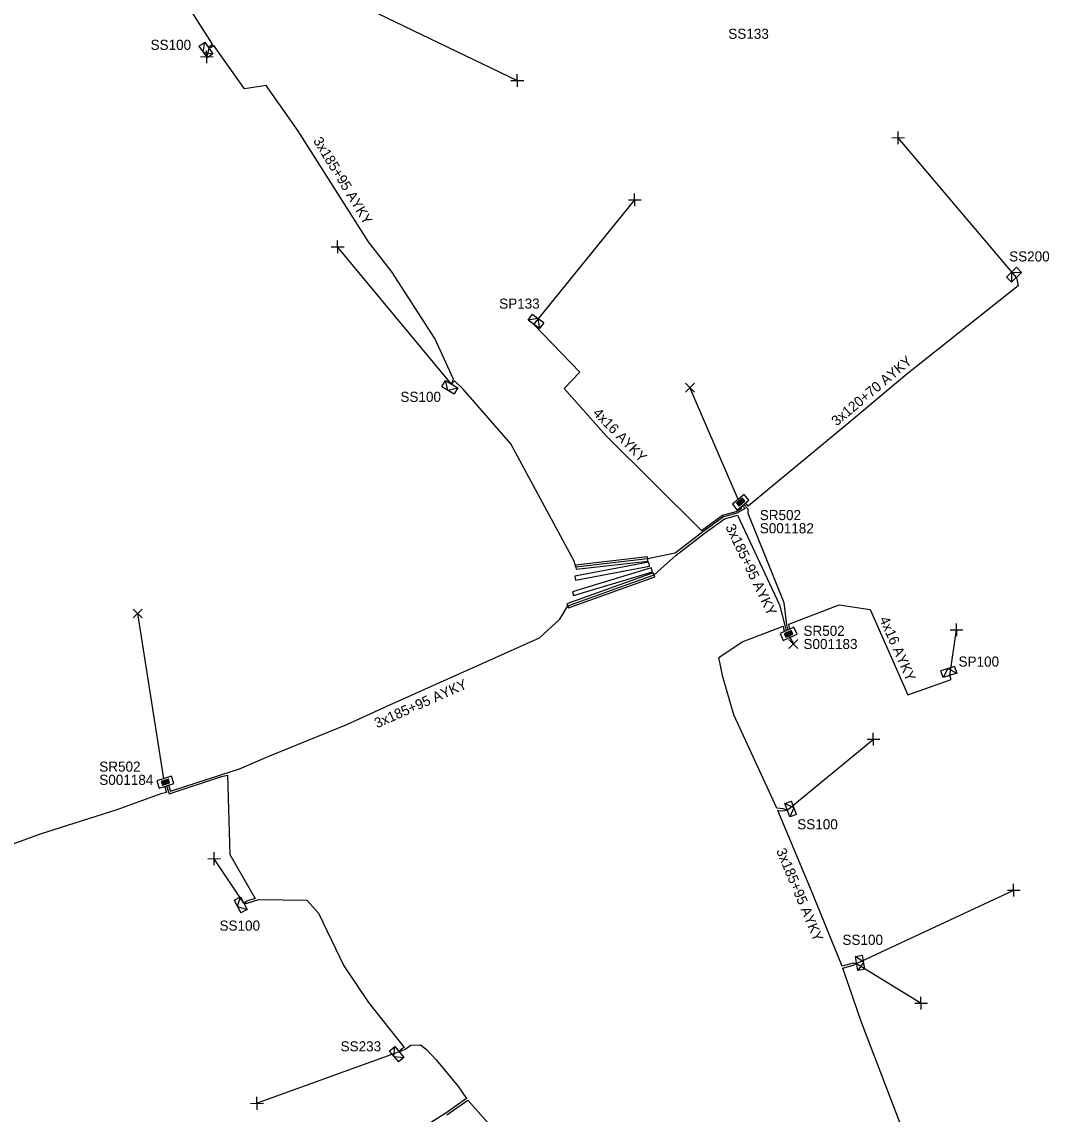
# Model space of a CAD drawing. Extents: x -762504 to -761250, y -1152974 to -1152253.
# Drawn here: x -761655.3 to -761554.2, y -1152498.6 to -1152391 of the extents above; entities that cross this region are included whole.
import ezdxf

# ---------------------------------------------------------------- set-up
doc = ezdxf.new("R2010")
doc.units = 0
for name, color, linetype in [('Vrstva 20', 7, 'Continuous'), ('Vrstva 28', 7, 'Continuous'), ('Vrstva 29', 7, 'Continuous'), ('Vrstva 30', 7, 'Continuous'), ('Vrstva 31', 7, 'Continuous'), ('Vrstva 33', 7, 'Continuous'), ('Vrstva 34', 7, 'Continuous'), ('Vrstva 5', 7, 'Continuous'), ('Vrstva 59', 7, 'Continuous'), ('Vrstva 6', 7, 'Continuous')]:
    doc.layers.add(name, color=color, linetype=linetype)

msp = doc.modelspace()

# ---------------------------------------------------------------- linework, layer by layer
at = {"layer": 'Vrstva 20'}
for points in [[(-761593.62, -1152444.18), (-761600.9, -1152445.56), (-761600.82, -1152445.96), (-761593.54, -1152444.58)], [(-761593.76, -1152443.68), (-761600.82, -1152444.49), (-761600.78, -1152444.89), (-761593.72, -1152444.08)], [(-761593.17, -1152445.25), (-761601.67, -1152448.3), (-761601.53, -1152448.68), (-761593.03, -1152445.63)], [(-761593.37, -1152444.75), (-761601.14, -1152447.11), (-761601.02, -1152447.49), (-761593.25, -1152445.13)]]:
    msp.add_lwpolyline(points, close=True, dxfattribs=at)
at = {"layer": 'Vrstva 28'}
for points in [[(-761584.237, -1152437.517), (-761585.386, -1152438.482)], [(-761584.4, -1152437.901), (-761584.97, -1152438.38)], [(-761584.406, -1152437.968), (-761584.904, -1152438.385)], [(-761584.904, -1152439.056), (-761583.755, -1152438.092)], [(-761584.412, -1152438.034), (-761584.837, -1152438.391)], [(-761584.418, -1152438.101), (-761584.771, -1152438.397)], [(-761584.357, -1152438.173), (-761584.418, -1152438.101)], [(-761584.291, -1152438.179), (-761584.412, -1152438.034)], [(-761584.224, -1152438.185), (-761584.406, -1152437.968)], [(-761584.157, -1152438.191), (-761584.4, -1152437.901)], [(-761583.755, -1152438.092), (-761584.237, -1152437.517)], [(-761585.386, -1152438.482), (-761584.904, -1152439.056)], [(-761584.97, -1152438.38), (-761584.728, -1152438.669)], [(-761584.904, -1152438.385), (-761584.722, -1152438.603)], [(-761584.837, -1152438.391), (-761584.716, -1152438.536)], [(-761584.771, -1152438.397), (-761584.71, -1152438.469)], [(-761584.728, -1152438.669), (-761584.157, -1152438.191)], [(-761584.722, -1152438.603), (-761584.224, -1152438.185)], [(-761584.716, -1152438.536), (-761584.291, -1152438.179)], [(-761584.71, -1152438.469), (-761584.357, -1152438.173)], [(-761584.419, -1152438.164), (-761584.709, -1152438.407)], [(-761579.33, -1152450.599), (-761580.689, -1152451.233)], [(-761579.6, -1152450.927), (-761580.275, -1152451.242)], [(-761579.623, -1152450.99), (-761580.212, -1152451.264)], [(-761579.503, -1152451.247), (-761579.623, -1152450.99)], [(-761579.441, -1152451.27), (-761579.6, -1152450.927)], [(-761579.013, -1152451.279), (-761579.33, -1152450.599)], [(-761580.689, -1152451.233), (-761580.372, -1152451.913)], [(-761580.372, -1152451.913), (-761579.013, -1152451.279)], [(-761580.275, -1152451.242), (-761580.115, -1152451.584)], [(-761580.212, -1152451.264), (-761580.092, -1152451.521)], [(-761579.646, -1152451.053), (-761580.149, -1152451.287)], [(-761580.149, -1152451.287), (-761580.069, -1152451.459)], [(-761580.115, -1152451.584), (-761579.441, -1152451.27)], [(-761580.092, -1152451.521), (-761579.503, -1152451.247)], [(-761579.669, -1152451.115), (-761580.086, -1152451.31)], [(-761580.086, -1152451.31), (-761580.046, -1152451.396)], [(-761580.069, -1152451.459), (-761579.566, -1152451.224)], [(-761580.046, -1152451.396), (-761579.629, -1152451.201)], [(-761580.029, -1152451.335), (-761579.686, -1152451.176)], [(-761579.629, -1152451.201), (-761579.669, -1152451.115)], [(-761579.566, -1152451.224), (-761579.646, -1152451.053)], [(-761640.619, -1152465.269), (-761642.046, -1152465.732)], [(-761642.046, -1152465.732), (-761641.814, -1152466.446)], [(-761641.814, -1152466.446), (-761640.388, -1152465.982)], [(-761640.915, -1152465.564), (-761641.623, -1152465.794)], [(-761641.623, -1152465.794), (-761641.506, -1152466.153)], [(-761640.945, -1152465.623), (-761641.563, -1152465.824)], [(-761641.563, -1152465.824), (-761641.475, -1152466.093)], [(-761641.506, -1152466.153), (-761640.798, -1152465.923)], [(-761640.975, -1152465.683), (-761641.503, -1152465.854)], [(-761641.503, -1152465.854), (-761641.445, -1152466.034)], [(-761641.475, -1152466.093), (-761640.858, -1152465.893)], [(-761641.445, -1152466.034), (-761640.917, -1152465.862)], [(-761641.006, -1152465.742), (-761641.444, -1152465.885)], [(-761641.444, -1152465.885), (-761641.415, -1152465.974)], [(-761641.415, -1152465.974), (-761640.977, -1152465.832)], [(-761641.031, -1152465.8), (-761641.39, -1152465.917)], [(-761640.977, -1152465.832), (-761641.006, -1152465.742)], [(-761640.917, -1152465.862), (-761640.975, -1152465.683)], [(-761640.858, -1152465.893), (-761640.945, -1152465.623)], [(-761640.798, -1152465.923), (-761640.915, -1152465.564)], [(-761640.388, -1152465.982), (-761640.619, -1152465.269)]]:
    msp.add_lwpolyline(points, dxfattribs=at)
at = {"layer": 'Vrstva 31'}
for points in [[(-761637.907, -1152393.376), (-761637.333, -1152392.974), (-761636.53, -1152394.121), (-761637.104, -1152394.523)], [(-761637.907, -1152393.376), (-761637.104, -1152394.523)], [(-761637.505, -1152393.949), (-761637.333, -1152392.974)], [(-761637.505, -1152393.949), (-761636.53, -1152394.121)], [(-761557.401, -1152415.148), (-761558.408, -1152416.12)], [(-761557.401, -1152415.148), (-761556.915, -1152415.651), (-761557.922, -1152416.624), (-761558.408, -1152416.12)], [(-761557.904, -1152415.634), (-761557.922, -1152416.624)], [(-761557.904, -1152415.634), (-761556.915, -1152415.651)], [(-761603.96, -1152420.617), (-761604.371, -1152421.183), (-761605.504, -1152420.36), (-761605.092, -1152419.794)], [(-761603.96, -1152420.617), (-761605.092, -1152419.794)], [(-761604.526, -1152420.205), (-761605.504, -1152420.36)], [(-761604.526, -1152420.205), (-761604.371, -1152421.183)], [(-761613.993, -1152426.888), (-761613.633, -1152426.288), (-761612.433, -1152427.009), (-761612.793, -1152427.609)], [(-761613.993, -1152426.888), (-761612.793, -1152427.609)], [(-761613.393, -1152427.249), (-761613.633, -1152426.288)], [(-761613.393, -1152427.249), (-761612.433, -1152427.009)], [(-761563.518, -1152454.457), (-761564.849, -1152454.889)], [(-761563.518, -1152454.457), (-761563.302, -1152455.122), (-761564.633, -1152455.555), (-761564.849, -1152454.889)], [(-761564.184, -1152454.673), (-761564.633, -1152455.555)], [(-761564.184, -1152454.673), (-761563.302, -1152455.122)], [(-761579.081, -1152469.051), (-761579.739, -1152469.29), (-761580.218, -1152467.975), (-761579.56, -1152467.735)], [(-761579.321, -1152468.393), (-761580.218, -1152467.975)], [(-761579.081, -1152469.051), (-761579.56, -1152467.735)], [(-761579.321, -1152468.393), (-761579.739, -1152469.29)], [(-761634.433, -1152477.482), (-761633.809, -1152477.164), (-761633.174, -1152478.411), (-761633.798, -1152478.729)], [(-761634.433, -1152477.482), (-761633.798, -1152478.729)], [(-761634.115, -1152478.105), (-761633.809, -1152477.164)], [(-761634.115, -1152478.105), (-761633.174, -1152478.411)], [(-761572.348, -1152484.281), (-761573.038, -1152484.402), (-761573.281, -1152483.023), (-761572.591, -1152482.902)], [(-761572.47, -1152483.591), (-761573.281, -1152483.023)], [(-761572.348, -1152484.281), (-761572.591, -1152482.902)], [(-761572.47, -1152483.591), (-761573.038, -1152484.402)], [(-761619.168, -1152492.352), (-761618.632, -1152491.902), (-761617.732, -1152492.974), (-761618.268, -1152493.424)], [(-761618.718, -1152492.888), (-761618.632, -1152491.902)], [(-761619.168, -1152492.352), (-761618.268, -1152493.424)], [(-761618.718, -1152492.888), (-761617.732, -1152492.974)]]:
    msp.add_lwpolyline(points, dxfattribs=at)
at = {"layer": 'Vrstva 34'}
for points in [[(-761637.129, -1152395.025), (-761637.151, -1152393.775)], [(-761637.765, -1152394.411), (-761636.515, -1152394.389)], [(-761606.549, -1152397.375), (-761606.571, -1152396.125)], [(-761607.185, -1152396.761), (-761605.935, -1152396.739)], [(-761569.685, -1152402.391), (-761568.435, -1152402.369)], [(-761569.049, -1152403.005), (-761569.071, -1152401.755)], [(-761594.989, -1152409.125), (-761595.011, -1152407.875)], [(-761595.625, -1152408.511), (-761594.375, -1152408.489)], [(-761624.875, -1152413.141), (-761623.625, -1152413.119)], [(-761624.239, -1152413.755), (-761624.261, -1152412.505)], [(-761590.002, -1152426.558), (-761589.118, -1152427.442)], [(-761590.002, -1152427.442), (-761589.118, -1152426.558)], [(-761644.382, -1152448.808), (-761643.498, -1152449.692)], [(-761644.382, -1152449.692), (-761643.498, -1152448.808)], [(-761563.935, -1152450.871), (-761562.685, -1152450.849)], [(-761563.299, -1152451.485), (-761563.321, -1152450.235)], [(-761579.822, -1152451.808), (-761578.938, -1152452.692)], [(-761579.822, -1152452.692), (-761578.938, -1152451.808)], [(-761572.125, -1152461.641), (-761570.875, -1152461.619)], [(-761571.489, -1152462.255), (-761571.511, -1152461.005)], [(-761637.035, -1152473.411), (-761635.785, -1152473.389)], [(-761636.399, -1152474.025), (-761636.421, -1152472.775)], [(-761558.315, -1152476.511), (-761557.065, -1152476.489)], [(-761557.679, -1152477.125), (-761557.701, -1152475.875)], [(-761566.799, -1152488.255), (-761566.821, -1152487.005)], [(-761567.435, -1152487.641), (-761566.185, -1152487.619)], [(-761632.179, -1152498.125), (-761632.201, -1152496.875)], [(-761632.815, -1152497.511), (-761631.565, -1152497.489)]]:
    msp.add_lwpolyline(points, dxfattribs=at)
at = {"layer": 'Vrstva 5'}
for points in [[(-761584.4, -1152438.64), (-761584.14, -1152438.91), (-761584.95, -1152439.38), (-761586.26, -1152439.74), (-761588.3, -1152441.21), (-761591.02, -1152443.31), (-761593.74, -1152443.88), (-761600.8, -1152444.69), (-761600.97, -1152444.11), (-761607.19, -1152432.53), (-761611.9, -1152427.16), (-761612.73, -1152426.33), (-761613.03, -1152426.65), (-761612.85, -1152426.15), (-761614.68, -1152422.17), (-761618.92, -1152415.59), (-761621.2, -1152412.64), (-761628.17, -1152401.66), (-761631.3, -1152397.23), (-761633.43, -1152397.55), (-761636.45, -1152393.31), (-761636.69, -1152393.49), (-761636.93, -1152393.55), (-761636.8, -1152393.32), (-761636.56, -1152393.15), (-761640, -1152387.78)], [(-761557.42, -1152416.14), (-761557.24, -1152416.98), (-761568.22, -1152425.66), (-761574.12, -1152430.62), (-761583.82, -1152438.67), (-761584.11, -1152438.36)], [(-761604.94, -1152420.77), (-761600.4, -1152425.46), (-761601.96, -1152427.1), (-761597.79, -1152431.78), (-761588.44, -1152441.07), (-761586.35, -1152439.56), (-761585.03, -1152439.19), (-761584.46, -1152438.87), (-761584.57, -1152438.75)], [(-761579.91, -1152450.9), (-761580.01, -1152450.38), (-761580.28, -1152448.21), (-761583.83, -1152439.39), (-761583.82, -1152438.96), (-761584.26, -1152438.5)], [(-761640.91, -1152466.15), (-761640.71, -1152466.76), (-761635.74, -1152465.13), (-761633.91, -1152464.55), (-761631.09, -1152463.35), (-761623.36, -1152460.17), (-761619.11, -1152458.23), (-761604.38, -1152451.65), (-761602.37, -1152449.8), (-761601.6, -1152448.49), (-761593.1, -1152445.44), (-761590.92, -1152443.49), (-761588.18, -1152441.37), (-761586.17, -1152439.92), (-761584.87, -1152439.56), (-761580.75, -1152448.39), (-761580.21, -1152450.42), (-761580.1, -1152450.97)], [(-761579.73, -1152450.81), (-761579.83, -1152450.29), (-761574.87, -1152448.38), (-761571.82, -1152448.87), (-761568.1, -1152457.27), (-761563.84, -1152455.76), (-761563.97, -1152455.34)], [(-761562.35, -1152511.19), (-761562.21, -1152511.6), (-761564.38, -1152511.85), (-761566.14, -1152507.05), (-761568.84, -1152499.56), (-761572.71, -1152489.44), (-761574.51, -1152484.19), (-761573.48, -1152483.9), (-761573.16, -1152483.71), (-761573.51, -1152483.7), (-761574.58, -1152484), (-761577.71, -1152476.35), (-761580.92, -1152468.65), (-761580.38, -1152468.69), (-761579.98, -1152468.63), (-761580.38, -1152468.49), (-761581.01, -1152468.44), (-761585.25, -1152459.23), (-761586.34, -1152455.49), (-761586.73, -1152453.58), (-761584.41, -1152452.04), (-761580.4, -1152450.51), (-761580.3, -1152451.05)], [(-761641.1, -1152466.21), (-761640.84, -1152467.01), (-761635.69, -1152465.32), (-761635.11, -1152465.19), (-761634.85, -1152472.98), (-761632.36, -1152477.32), (-761633.2, -1152477.59), (-761633.49, -1152477.79), (-761633.15, -1152477.78), (-761632, -1152477.41), (-761627.3, -1152477.48), (-761626.13, -1152478.77), (-761623.63, -1152483.96), (-761621.21, -1152487.57), (-761617.71, -1152491.99), (-761617.99, -1152492.18), (-761618.18, -1152492.44)], [(-761641.29, -1152466.27), (-761641.1, -1152466.87), (-761641.67, -1152467.01), (-761646, -1152468.58), (-761653.53, -1152470.98), (-761663.99, -1152474.81), (-761669.68, -1152477.3), (-761671.82, -1152478.31), (-761677.04, -1152480.76), (-761677.28, -1152480.27), (-761677.22, -1152480.83), (-761690.99, -1152485.68), (-761696.92, -1152487.72), (-761697.28, -1152487.3), (-761697.33, -1152487.77), (-761698.06, -1152488.07), (-761698.03, -1152489.06), (-761702.19, -1152490.71), (-761706.38, -1152492.07), (-761707.93, -1152490.1)], [(-761618.18, -1152492.44), (-761617.59, -1152492.15), (-761617.06, -1152491.76), (-761616.09, -1152491.74), (-761615.49, -1152492.19), (-761614.56, -1152493.21), (-761612.36, -1152495.89), (-761611.55, -1152497.03), (-761613.61, -1152498.47), (-761615.28, -1152499.51)], [(-761613.5, -1152498.63), (-761611.42, -1152497.19), (-761608.9, -1152500.06)]]:
    msp.add_lwpolyline(points, dxfattribs=at)
at = {"layer": 'Vrstva 59'}
for points in [[(-761628.07, -1152386.37), (-761606.56, -1152396.75)], [(-761636.93, -1152393.55), (-761637.14, -1152394.4)], [(-761557.42, -1152416.14), (-761569.06, -1152402.38)], [(-761604.94, -1152420.77), (-761595, -1152408.5)], [(-761613.03, -1152426.65), (-761624.25, -1152413.13)], [(-761584.79, -1152438.07), (-761589.56, -1152427)], [(-761641.36, -1152465.55), (-761643.94, -1152449.25)], [(-761563.97, -1152455.34), (-761563.31, -1152450.86)], [(-761579.83, -1152451.38), (-761579.38, -1152452.25)], [(-761579.98, -1152468.63), (-761571.5, -1152461.63)], [(-761633.49, -1152477.79), (-761636.41, -1152473.4)], [(-761573.16, -1152483.71), (-761557.69, -1152476.5)], [(-761573.16, -1152483.71), (-761566.81, -1152487.63)], [(-761618.18, -1152492.44), (-761632.19, -1152497.5)]]:
    msp.add_lwpolyline(points, dxfattribs=at)

# ---------------------------------------------------------------- texts
at = {"layer": 'Vrstva 29'}
for s, p in [('S001182', (-761582.69, -1152441.35)), ('S001183', (-761578.39, -1152452.75)), ('S001184', (-761647.72, -1152466.13))]:
    msp.add_text(s, height=0.9943, dxfattribs=at).set_placement(p)
at = {"layer": 'Vrstva 30'}
for p in [(-761582.69, -1152440.05), (-761578.39, -1152451.45), (-761647.72, -1152464.83)]:
    msp.add_text('SR502', height=0.9943, dxfattribs=at).set_placement(p)
at = {"layer": 'Vrstva 33'}
for s, p in [('SS133', (-761585.79, -1152392.64)), ('SS100', (-761642.67, -1152393.73)), ('SS200', (-761558.14, -1152414.57)), ('SP133', (-761608.35, -1152419.22)), ('SS100', (-761618.07, -1152428.4)), ('SP100', (-761563.12, -1152454.48)), ('SS100', (-761579, -1152470.51)), ('SS100', (-761635.88, -1152480.49)), ('SS100', (-761574.55, -1152481.89)), ('SS233', (-761623.96, -1152492.38))]:
    msp.add_text(s, height=0.9943, dxfattribs=at).set_placement(p)
at = {"layer": 'Vrstva 6'}
for s, height, rotation, p in [('3x185+95 AYKY', 0.99429, 301.35247, (-761626.7, -1152402.68)), ('3x120+70 AYKY', 0.99429, 39.94298, (-761575.12, -1152430.83)), ('4x16 AYKY', 0.9943, 314.61024, (-761599.19, -1152429.59)), ('3x185+95 AYKY', 0.99428, 295.44801, (-761586.09, -1152440.72)), ('4x16 AYKY', 0.9943, 293.76983, (-761570.94, -1152449.8)), ('3x185+95 AYKY', 0.99428, 24.07989, (-761620.36, -1152460.57)), ('3x185+95 AYKY', 0.99429, 292.56962, (-761581.09, -1152472.61))]:
    msp.add_text(s, height=height, rotation=rotation, dxfattribs=at).set_placement(p)

doc.saveas('drawing.dxf')
